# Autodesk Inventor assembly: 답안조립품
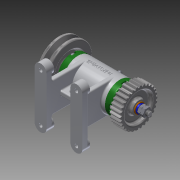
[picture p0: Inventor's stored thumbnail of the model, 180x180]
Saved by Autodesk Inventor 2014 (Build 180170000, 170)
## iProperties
Created: 2015-11
Part Number: 답안조립품
Document SubType Name: Assembly
Designer: Owner
Author: Owner
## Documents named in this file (14)
- C:\Documents and Settings\Owner\바탕 화면\451109V1020\답안조립품.iam
- C:\Documents and Settings\Owner\바탕 화면\451109V1020\본체.ipt
- C:\Documents and Settings\Owner\바탕 화면\451109V1020\커버.ipt
- C:\Documents and Settings\Owner\바탕 화면\451109V1020\베어링 15 x 32 x 9.ipt
- C:\Documents and Settings\Owner\바탕 화면\451109V1020\축.ipt
- C:\Documents and Settings\Owner\바탕 화면\451109V1020\오일 실 15 25 7.ipt
- C:\Documents and Settings\Owner\바탕 화면\451109V1020\볼트 M4 x 12.ipt
- C:\Documents and Settings\Owner\바탕 화면\451109V1020\V벨트풀리.ipt
- C:\Documents and Settings\Owner\바탕 화면\451109V1020\스퍼기어.ipt
- C:\Documents and Settings\Owner\바탕 화면\451109V1020\와셔 6x11.5.ipt
- C:\Documents and Settings\Owner\바탕 화면\451109V1020\스프링와셔 8.ipt
- C:\Documents and Settings\Owner\바탕 화면\451109V1020\너트 M 8.ipt
- C:\Documents and Settings\Owner\바탕 화면\451109V1020\니플 M 6 x 0.75.ipt
- C:\Documents and Settings\Owner\바탕 화면\451109V1020\와셔 8x17.ipt
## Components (19 placed, 3 different names)
1. KS B 2023 6002 - 15 x 32 x 9:1
2. KS B 2023 6002 - 15 x 32 x 9:2
3. ISO 4762 M4 x 12:5
4. ISO 4762 M4 x 12:6
5. ISO 4762 M4 x 12:7
6. ISO 4762 M4 x 12:8
7. ISO 4762 M4 x 12:9
8. ISO 4762 M4 x 12:10
9. ISO 4762 M4 x 12:11
10. ISO 4762 M4 x 12:12
11. V벨트풀리:1
12. ISO 4762 M4 x 12:1
13. ISO 4762 M4 x 12:2
14. ISO 4762 M4 x 12:3
15. ISO 4762 M4 x 12:4
16. ISO 4762 M4 x 12:13
17. ISO 4762 M4 x 12:14
18. ISO 4762 M4 x 12:15
19. ISO 4762 M4 x 12:16
